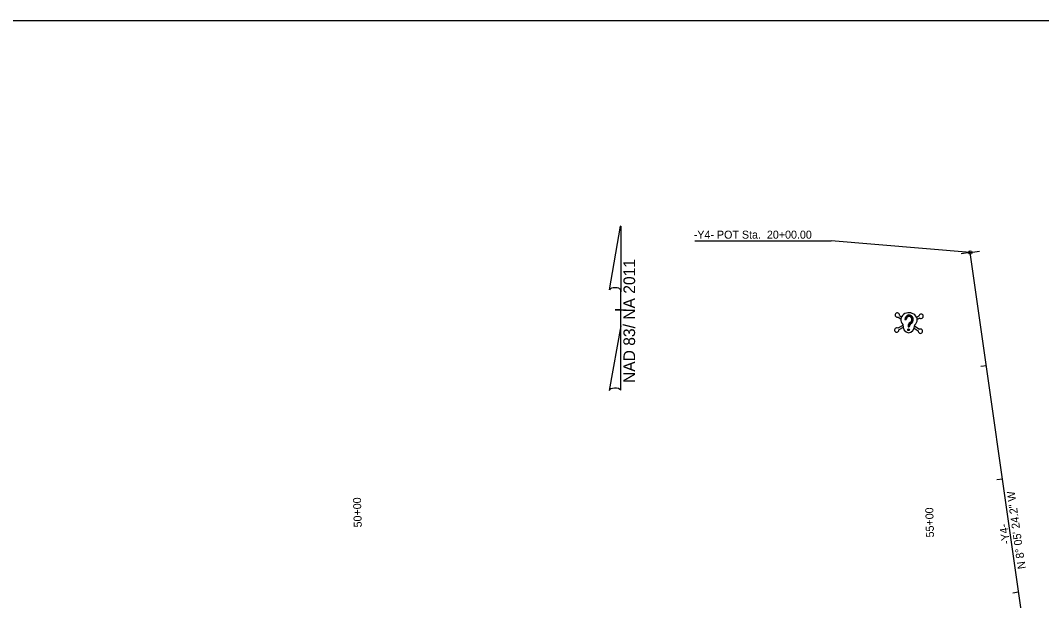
# Model space of a CAD drawing. Extents: x 1755545 to 1761252, y 736169 to 737766.
# Drawn here: x 1759380 to 1760273, y 737259 to 737766 of the extents above; entities that cross this region are included whole.
import ezdxf

# ---------------------------------------------------------------- set-up
doc = ezdxf.new("R2010")
doc.units = 0
for name, color, linetype in [('Default', 7, 'Continuous'), ('Prop Horizontal Alignment', 7, 'Continuous'), ('Prop Horizontal Alignment Direction Label', 7, 'Continuous'), ('Prop Horizontal Alignment Station Label', 7, 'Continuous'), ('Prop Horizontal Alignment Tick Label', 7, 'Continuous'), ('Prop Horizontal Alignment Tick Large', 7, 'Continuous'), ('Prop Horizontal Alignment Tick Small', 7, 'Continuous'), ('Prop North Arrow NAD83 for Plan Sheets CELL', 7, 'Continuous'), ('Scratch_Level_5', 7, 'Continuous')]:
    doc.layers.add(name, color=color, linetype=linetype)

msp = doc.modelspace()

# ---------------------------------------------------------------- linework, layer by layer
at = {"layer": 'Default'}
for p, q in [((1760147.7, 737506.57), (1760150.02, 737504.95)), ((1760148.72, 737508.03), (1760150.59, 737506.72)), ((1760153.41, 737504.45), (1760154.54, 737504.4)), ((1760165.75, 737507.21), (1760163.76, 737506.08)), ((1760166.63, 737505.65), (1760164.16, 737504.26)), ((1760151.53, 737499.2), (1760147.22, 737496.77)), ((1760151.84, 737497.33), (1760148.1, 737495.22)), ((1760156.25, 737498.96), (1760156.2, 737497.96)), ((1760156.2, 737497.96), (1760157.33, 737497.91)), ((1760156.41, 737498.95), (1760156.36, 737497.95)), ((1760156.57, 737498.94), (1760156.52, 737497.95)), ((1760156.73, 737498.93), (1760156.69, 737497.94)), ((1760156.9, 737498.92), (1760156.85, 737497.93)), ((1760156.95, 737501.79), (1760156.95, 737501.79)), ((1760157.06, 737498.92), (1760157.01, 737497.92)), ((1760157.22, 737498.91), (1760157.17, 737497.91)), ((1760157.38, 737498.9), (1760157.33, 737497.91)), ((1760161.61, 737496.86), (1760165.13, 737494.4)), ((1760162.1, 737498.69), (1760166.15, 737495.86))]:
    msp.add_line(p, q, dxfattribs=at)
for radius in [0.81, 0.63, 0.446, 0.266, 0.0863]:
    msp.add_circle((1760156.69, 737495.47), radius, dxfattribs=at)
for centre, start, end in [((1760146.83, 737508.26), 353.12417, 297.03272), ((1760167.65, 737507.25), 237.42038, 181.32894), ((1760146.2, 737495.18), 57.42038, 1.32894), ((1760167.02, 737494.17), 173.12417, 117.03272)]:
    msp.add_arc(centre, 1.9, start, end, dxfattribs=at)
for centre, major_axis, ratio, start_param, end_param in [((1760157.06, 737504.04), (7.1, -0.34), 0.885014, 5.564242, 10.143721), ((1760157.07, 737504.28), (0.2, 4.08), 0.9, 3.567618, 7.853982), ((1760157.07, 737504.28), (0.19, 3.9), 0.9, 3.567618, 7.853982), ((1760157.07, 737504.28), (0.18, 3.72), 0.9, 3.567618, 7.853982), ((1760157.07, 737504.28), (0.17, 3.54), 0.9, 3.567618, 7.853982), ((1760157.07, 737504.28), (0.16, 3.36), 0.9, 3.567618, 7.853982), ((1760157.07, 737504.28), (0.15, 3.18), 0.9, 3.567618, 7.853982), ((1760157.07, 737504.28), (0.15, 3), 0.9, 3.567618, 7.853982), ((1760157.07, 737504.28), (0.14, 2.82), 0.9, 3.567618, 7.853982), ((1760156.86, 737499.97), (-0.34, -7.1), 0.752542, 4.722735, 7.843636), ((1760159, 737498.82), (0.15, 3.06), 0.9, 0.426026, 1.570796), ((1760159, 737498.82), (0.14, 2.88), 0.9, 0.426026, 1.570796), ((1760159, 737498.82), (0.13, 2.7), 0.9, 0.426026, 1.570796), ((1760159, 737498.82), (0.12, 2.52), 0.9, 0.426026, 1.570796), ((1760159, 737498.82), (0.11, 2.34), 0.9, 0.426026, 1.570796), ((1760159, 737498.82), (0.1, 2.16), 0.9, 0.426026, 1.570796), ((1760159, 737498.82), (0.1, 1.98), 0.9, 0.426026, 1.570796), ((1760159, 737498.82), (0.09, 1.8), 0.9, 0.426026, 1.570796)]:
    msp.add_ellipse(centre, major_axis=major_axis, ratio=ratio, start_param=start_param, end_param=end_param, dxfattribs=at)
at = {"layer": 'Prop Horizontal Alignment'}
msp.add_line((1760351.41, 736572.88), (1760210.68, 737562.93), dxfattribs=at)
at = {"layer": 'Prop Horizontal Alignment Station Label'}
for p in [(1759969.78, 737573.12), (1760210.68, 737562.93)]:
    msp.add_line(p, (1760089, 737573.12), dxfattribs=at)
msp.add_circle((1760210.68, 737562.93), 1.5, dxfattribs=at)
at = {"layer": 'Prop Horizontal Alignment Tick Large'}
for q in [(1760202.76, 737561.81), (1760218.6, 737564.06)]:
    msp.add_line((1760210.68, 737562.93), q, dxfattribs=at)
at = {"layer": 'Prop Horizontal Alignment Tick Small'}
for p, q in [((1760224.75, 737463.93), (1760219.8, 737463.22)), ((1760238.83, 737364.92), (1760233.88, 737364.22)), ((1760252.9, 737265.92), (1760247.95, 737265.21))]:
    msp.add_line(p, q, dxfattribs=at)
at = {"layer": 'Prop North Arrow NAD83 for Plan Sheets CELL'}
for p, q in [((1759894.92, 737530.44), (1759904.76, 737586.06)), ((1759904.82, 737586.06), (1759904.76, 737586.06)), ((1759904.82, 737586.06), (1759904.76, 737586.06)), ((1759904.82, 737586.06), (1759904.82, 737528.7)), ((1759904.82, 737498.94), (1759904.82, 737530.38)), ((1759904.82, 737528.7), (1759904.82, 737530.32)), ((1759900.02, 737512.86), (1759899.96, 737512.86)), ((1759904.28, 737512.86), (1759900.02, 737512.86)), ((1759900.08, 737512.86), (1759909.68, 737512.86)), ((1759904.82, 737498.94), (1759894.8, 737442.24)), ((1759904.88, 737442.48), (1759904.82, 737498.94))]:
    msp.add_line(p, q, dxfattribs=at)
for centre, start_param, end_param in [((1759899.89, 737529.85), 0.216388, 2.908219), ((1759899.89, 737442.05), 0.201328, 3.141593)]:
    msp.add_ellipse(centre, major_axis=(5.08, -0.04), ratio=0.461098, start_param=start_param, end_param=end_param, dxfattribs=at)
at = {"layer": 'Scratch_Level_5'}
msp.add_lwpolyline([(1759122.38, 737765.89), (1760563.07, 737765.89), (1760563.07, 736805.42), (1759122.38, 736805.42)], close=True, dxfattribs=at)

# ---------------------------------------------------------------- texts
at = {"layer": 'Prop Horizontal Alignment Direction Label'}
for s, p in [('N 8%%d 05\' 24.2" W', (1760259.18, 737286.65)), ('-Y4-', (1760245.29, 737308.48))]:
    msp.add_text(s, height=7, rotation=98.09005, dxfattribs=at).set_placement(p)
at = {"layer": 'Prop Horizontal Alignment Station Label'}
msp.add_text('-Y4- POT Sta.  20+00.00', height=7, rotation=360, dxfattribs=at).set_placement((1759968.76, 737575.07))
at = {"layer": 'Prop Horizontal Alignment Tick Label'}
for s, p in [('50+00', (1759678.38, 737322.65)), ('55+00', (1760178.95, 737313.89))]:
    msp.add_text(s, height=7, rotation=91.62654, dxfattribs=at).set_placement(p)
at = {"layer": 'Prop North Arrow NAD83 for Plan Sheets CELL'}
msp.add_text('NAD 83/ NA 2011', height=10.2, rotation=90, dxfattribs=at).set_placement((1759917.45, 737448.84))

doc.saveas('drawing.dxf')
